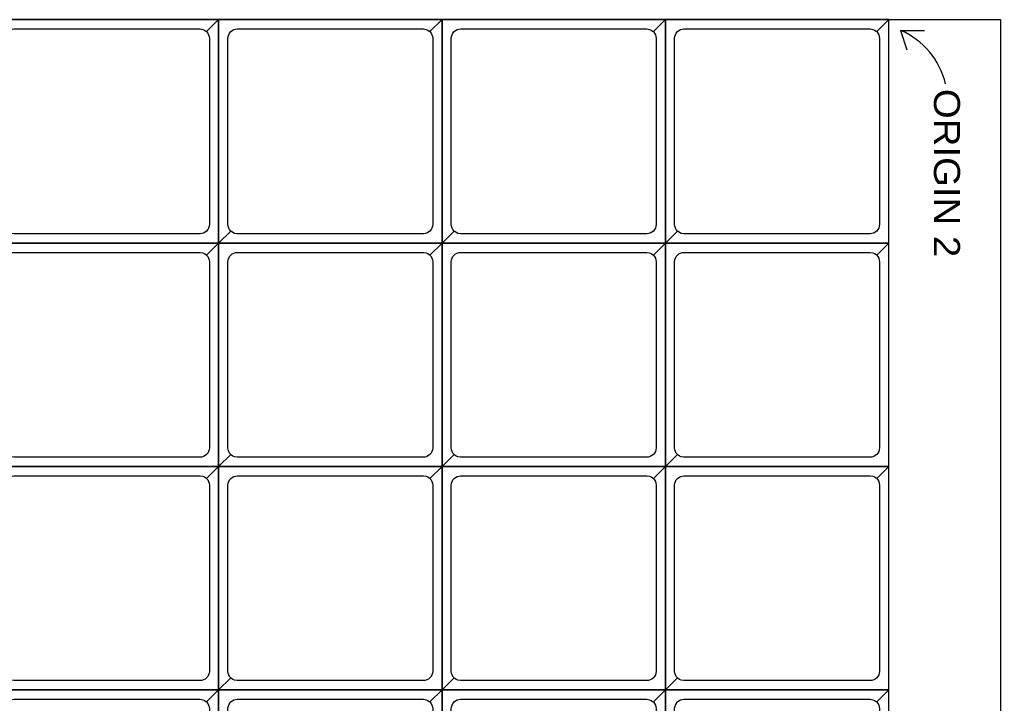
# Model space of a CAD drawing. Extents: x 67896 to 67908, y 49158.5 to 49162.6.
# Drawn here: x 67905.354 to 67907.989, y 49160.797 to 49162.633 of the extents above; entities that cross this region are included whole.
import ezdxf
from ezdxf.enums import TextEntityAlignment as Align

# ---------------------------------------------------------------- set-up
doc = ezdxf.new("R2010")
doc.units = 0
doc.header["$LTSCALE"] = 0.02
for name, color, linetype, lineweight in [('1', 7, 'Continuous', 25), ('2', 7, 'Continuous', 25), ('3', 7, 'Continuous', 25), ('4', 7, 'Continuous', 25), ('5', 7, 'Continuous', 25)]:
    doc.layers.add(name, color=color, linetype=linetype, lineweight=lineweight)

msp = doc.modelspace()

# ---------------------------------------------------------------- linework, layer by layer
at = {"layer": '1'}
for points in [[(67905.2889, 49162.0331), (67905.8889, 49162.0331), (67905.8889, 49162.6331), (67905.2889, 49162.6331)], [(67905.8889, 49162.0331), (67906.4889, 49162.0331), (67906.4889, 49162.6331), (67905.8889, 49162.6331)], [(67906.4889, 49162.0331), (67907.0889, 49162.0331), (67907.0889, 49162.6331), (67906.4889, 49162.6331)], [(67907.0889, 49162.0331), (67907.6889, 49162.0331), (67907.6889, 49162.6331), (67907.0889, 49162.6331)], [(67905.2889, 49161.4331), (67905.8889, 49161.4331), (67905.8889, 49162.0331), (67905.2889, 49162.0331)], [(67905.8889, 49161.4331), (67906.4889, 49161.4331), (67906.4889, 49162.0331), (67905.8889, 49162.0331)], [(67906.4889, 49161.4331), (67907.0889, 49161.4331), (67907.0889, 49162.0331), (67906.4889, 49162.0331)], [(67907.0889, 49161.4331), (67907.6889, 49161.4331), (67907.6889, 49162.0331), (67907.0889, 49162.0331)], [(67905.2889, 49160.8331), (67905.8889, 49160.8331), (67905.8889, 49161.4331), (67905.2889, 49161.4331)], [(67905.8889, 49160.8331), (67906.4889, 49160.8331), (67906.4889, 49161.4331), (67905.8889, 49161.4331)], [(67906.4889, 49160.8331), (67907.0889, 49160.8331), (67907.0889, 49161.4331), (67906.4889, 49161.4331)], [(67907.0889, 49160.8331), (67907.6889, 49160.8331), (67907.6889, 49161.4331), (67907.0889, 49161.4331)], [(67905.2889, 49160.2331), (67905.8889, 49160.2331), (67905.8889, 49160.8331), (67905.2889, 49160.8331)], [(67905.8889, 49160.2331), (67906.4889, 49160.2331), (67906.4889, 49160.8331), (67905.8889, 49160.8331)], [(67906.4889, 49160.2331), (67907.0889, 49160.2331), (67907.0889, 49160.8331), (67906.4889, 49160.8331)], [(67907.0889, 49160.2331), (67907.6889, 49160.2331), (67907.6889, 49160.8331), (67907.0889, 49160.8331)]]:
    msp.add_lwpolyline(points, close=True, dxfattribs=at)
at = {"layer": '2'}
for points in [[(67907.9889, 49159.0331), (67895.9889, 49159.0331), (67895.9889, 49162.6331), (67907.9889, 49162.6331)], [(67905.2889, 49162.0331), (67905.8889, 49162.0331), (67905.8889, 49162.6331), (67905.2889, 49162.6331)], [(67905.8889, 49162.0331), (67906.4889, 49162.0331), (67906.4889, 49162.6331), (67905.8889, 49162.6331)], [(67906.4889, 49162.0331), (67907.0889, 49162.0331), (67907.0889, 49162.6331), (67906.4889, 49162.6331)], [(67907.0889, 49162.0331), (67907.6889, 49162.0331), (67907.6889, 49162.6331), (67907.0889, 49162.6331)], [(67905.2889, 49161.4331), (67905.8889, 49161.4331), (67905.8889, 49162.0331), (67905.2889, 49162.0331)], [(67905.8889, 49161.4331), (67906.4889, 49161.4331), (67906.4889, 49162.0331), (67905.8889, 49162.0331)], [(67906.4889, 49161.4331), (67907.0889, 49161.4331), (67907.0889, 49162.0331), (67906.4889, 49162.0331)], [(67907.0889, 49161.4331), (67907.6889, 49161.4331), (67907.6889, 49162.0331), (67907.0889, 49162.0331)], [(67905.2889, 49160.8331), (67905.8889, 49160.8331), (67905.8889, 49161.4331), (67905.2889, 49161.4331)], [(67905.8889, 49160.8331), (67906.4889, 49160.8331), (67906.4889, 49161.4331), (67905.8889, 49161.4331)], [(67906.4889, 49160.8331), (67907.0889, 49160.8331), (67907.0889, 49161.4331), (67906.4889, 49161.4331)], [(67907.0889, 49160.8331), (67907.6889, 49160.8331), (67907.6889, 49161.4331), (67907.0889, 49161.4331)], [(67905.2889, 49160.2331), (67905.8889, 49160.2331), (67905.8889, 49160.8331), (67905.2889, 49160.8331)], [(67905.8889, 49160.2331), (67906.4889, 49160.2331), (67906.4889, 49160.8331), (67905.8889, 49160.8331)], [(67906.4889, 49160.2331), (67907.0889, 49160.2331), (67907.0889, 49160.8331), (67906.4889, 49160.8331)], [(67907.0889, 49160.2331), (67907.6889, 49160.2331), (67907.6889, 49160.8331), (67907.0889, 49160.8331)]]:
    msp.add_lwpolyline(points, close=True, dxfattribs=at)
at = {"layer": '3'}
for points in [[(67905.8889, 49162.6331), (67905.2889, 49162.6331), (67905.2889, 49162.0331), (67905.3212, 49162.0654), (67905.3181, 49162.0692), (67905.3158, 49162.0735), (67905.3144, 49162.0782), (67905.3139, 49162.0831), (67905.3139, 49162.5831), (67905.3144, 49162.588), (67905.3158, 49162.5927), (67905.3181, 49162.597), (67905.3212, 49162.6008), (67905.3212, 49162.6008), (67905.325, 49162.6039), (67905.3293, 49162.6062), (67905.334, 49162.6076), (67905.3389, 49162.6081), (67905.8389, 49162.6081), (67905.8462, 49162.607), (67905.8507, 49162.6051), (67905.8548, 49162.6024), (67905.8566, 49162.6008)], [(67906.4889, 49162.6331), (67905.8889, 49162.6331), (67905.8889, 49162.0331), (67905.9212, 49162.0654), (67905.9181, 49162.0692), (67905.9158, 49162.0735), (67905.9144, 49162.0782), (67905.9139, 49162.0831), (67905.9139, 49162.5831), (67905.9144, 49162.588), (67905.9158, 49162.5927), (67905.9181, 49162.597), (67905.9212, 49162.6008), (67905.9212, 49162.6008), (67905.925, 49162.6039), (67905.9293, 49162.6062), (67905.934, 49162.6076), (67905.9389, 49162.6081), (67906.4389, 49162.6081), (67906.4462, 49162.607), (67906.4507, 49162.6051), (67906.4548, 49162.6024), (67906.4566, 49162.6008)], [(67907.0889, 49162.6331), (67906.4889, 49162.6331), (67906.4889, 49162.0331), (67906.5212, 49162.0654), (67906.5181, 49162.0692), (67906.5158, 49162.0735), (67906.5144, 49162.0782), (67906.5139, 49162.0831), (67906.5139, 49162.5831), (67906.5144, 49162.588), (67906.5158, 49162.5927), (67906.5181, 49162.597), (67906.5212, 49162.6008), (67906.5212, 49162.6008), (67906.525, 49162.6039), (67906.5293, 49162.6062), (67906.534, 49162.6076), (67906.5389, 49162.6081), (67907.0389, 49162.6081), (67907.0462, 49162.607), (67907.0507, 49162.6051), (67907.0548, 49162.6024), (67907.0566, 49162.6008)], [(67907.6889, 49162.6331), (67907.0889, 49162.6331), (67907.0889, 49162.0331), (67907.1212, 49162.0654), (67907.1181, 49162.0692), (67907.1158, 49162.0735), (67907.1144, 49162.0782), (67907.1139, 49162.0831), (67907.1139, 49162.5831), (67907.1144, 49162.588), (67907.1158, 49162.5927), (67907.1181, 49162.597), (67907.1212, 49162.6008), (67907.1212, 49162.6008), (67907.125, 49162.6039), (67907.1293, 49162.6062), (67907.134, 49162.6076), (67907.1389, 49162.6081), (67907.6389, 49162.6081), (67907.6462, 49162.607), (67907.6507, 49162.6051), (67907.6548, 49162.6024), (67907.6566, 49162.6008)], [(67905.8889, 49162.0331), (67905.2889, 49162.0331), (67905.2889, 49161.4331), (67905.3212, 49161.4654), (67905.3181, 49161.4692), (67905.3158, 49161.4735), (67905.3144, 49161.4782), (67905.3139, 49161.4831), (67905.3139, 49161.9831), (67905.3144, 49161.988), (67905.3158, 49161.9927), (67905.3181, 49161.997), (67905.3212, 49162.0008), (67905.3212, 49162.0008), (67905.325, 49162.0039), (67905.3293, 49162.0062), (67905.334, 49162.0076), (67905.3389, 49162.0081), (67905.8389, 49162.0081), (67905.8462, 49162.007), (67905.8507, 49162.0051), (67905.8548, 49162.0024), (67905.8566, 49162.0008)], [(67906.4889, 49162.0331), (67905.8889, 49162.0331), (67905.8889, 49161.4331), (67905.9212, 49161.4654), (67905.9181, 49161.4692), (67905.9158, 49161.4735), (67905.9144, 49161.4782), (67905.9139, 49161.4831), (67905.9139, 49161.9831), (67905.9144, 49161.988), (67905.9158, 49161.9927), (67905.9181, 49161.997), (67905.9212, 49162.0008), (67905.9212, 49162.0008), (67905.925, 49162.0039), (67905.9293, 49162.0062), (67905.934, 49162.0076), (67905.9389, 49162.0081), (67906.4389, 49162.0081), (67906.4462, 49162.007), (67906.4507, 49162.0051), (67906.4548, 49162.0024), (67906.4566, 49162.0008)], [(67907.0889, 49162.0331), (67906.4889, 49162.0331), (67906.4889, 49161.4331), (67906.5212, 49161.4654), (67906.5181, 49161.4692), (67906.5158, 49161.4735), (67906.5144, 49161.4782), (67906.5139, 49161.4831), (67906.5139, 49161.9831), (67906.5144, 49161.988), (67906.5158, 49161.9927), (67906.5181, 49161.997), (67906.5212, 49162.0008), (67906.5212, 49162.0008), (67906.525, 49162.0039), (67906.5293, 49162.0062), (67906.534, 49162.0076), (67906.5389, 49162.0081), (67907.0389, 49162.0081), (67907.0462, 49162.007), (67907.0507, 49162.0051), (67907.0548, 49162.0024), (67907.0566, 49162.0008)], [(67907.6889, 49162.0331), (67907.0889, 49162.0331), (67907.0889, 49161.4331), (67907.1212, 49161.4654), (67907.1181, 49161.4692), (67907.1158, 49161.4735), (67907.1144, 49161.4782), (67907.1139, 49161.4831), (67907.1139, 49161.9831), (67907.1144, 49161.988), (67907.1158, 49161.9927), (67907.1181, 49161.997), (67907.1212, 49162.0008), (67907.1212, 49162.0008), (67907.125, 49162.0039), (67907.1293, 49162.0062), (67907.134, 49162.0076), (67907.1389, 49162.0081), (67907.6389, 49162.0081), (67907.6462, 49162.007), (67907.6507, 49162.0051), (67907.6548, 49162.0024), (67907.6566, 49162.0008)], [(67905.8889, 49161.4331), (67905.2889, 49161.4331), (67905.2889, 49160.8331), (67905.3212, 49160.8654), (67905.3181, 49160.8692), (67905.3158, 49160.8735), (67905.3144, 49160.8782), (67905.3139, 49160.8831), (67905.3139, 49161.3831), (67905.3144, 49161.388), (67905.3158, 49161.3927), (67905.3181, 49161.397), (67905.3212, 49161.4008), (67905.3212, 49161.4008), (67905.325, 49161.4039), (67905.3293, 49161.4062), (67905.334, 49161.4076), (67905.3389, 49161.4081), (67905.8389, 49161.4081), (67905.8462, 49161.407), (67905.8507, 49161.4051), (67905.8548, 49161.4024), (67905.8566, 49161.4008)], [(67906.4889, 49161.4331), (67905.8889, 49161.4331), (67905.8889, 49160.8331), (67905.9212, 49160.8654), (67905.9181, 49160.8692), (67905.9158, 49160.8735), (67905.9144, 49160.8782), (67905.9139, 49160.8831), (67905.9139, 49161.3831), (67905.9144, 49161.388), (67905.9158, 49161.3927), (67905.9181, 49161.397), (67905.9212, 49161.4008), (67905.9212, 49161.4008), (67905.925, 49161.4039), (67905.9293, 49161.4062), (67905.934, 49161.4076), (67905.9389, 49161.4081), (67906.4389, 49161.4081), (67906.4462, 49161.407), (67906.4507, 49161.4051), (67906.4548, 49161.4024), (67906.4566, 49161.4008)], [(67907.0889, 49161.4331), (67906.4889, 49161.4331), (67906.4889, 49160.8331), (67906.5212, 49160.8654), (67906.5181, 49160.8692), (67906.5158, 49160.8735), (67906.5144, 49160.8782), (67906.5139, 49160.8831), (67906.5139, 49161.3831), (67906.5144, 49161.388), (67906.5158, 49161.3927), (67906.5181, 49161.397), (67906.5212, 49161.4008), (67906.5212, 49161.4008), (67906.525, 49161.4039), (67906.5293, 49161.4062), (67906.534, 49161.4076), (67906.5389, 49161.4081), (67907.0389, 49161.4081), (67907.0462, 49161.407), (67907.0507, 49161.4051), (67907.0548, 49161.4024), (67907.0566, 49161.4008)], [(67907.6889, 49161.4331), (67907.0889, 49161.4331), (67907.0889, 49160.8331), (67907.1212, 49160.8654), (67907.1181, 49160.8692), (67907.1158, 49160.8735), (67907.1144, 49160.8782), (67907.1139, 49160.8831), (67907.1139, 49161.3831), (67907.1144, 49161.388), (67907.1158, 49161.3927), (67907.1181, 49161.397), (67907.1212, 49161.4008), (67907.1212, 49161.4008), (67907.125, 49161.4039), (67907.1293, 49161.4062), (67907.134, 49161.4076), (67907.1389, 49161.4081), (67907.6389, 49161.4081), (67907.6462, 49161.407), (67907.6507, 49161.4051), (67907.6548, 49161.4024), (67907.6566, 49161.4008)], [(67905.8889, 49160.8331), (67905.2889, 49160.8331), (67905.2889, 49160.2331), (67905.3212, 49160.2654), (67905.3181, 49160.2692), (67905.3158, 49160.2735), (67905.3144, 49160.2782), (67905.3139, 49160.2831), (67905.3139, 49160.7831), (67905.3144, 49160.788), (67905.3158, 49160.7927), (67905.3181, 49160.797), (67905.3212, 49160.8008), (67905.3212, 49160.8008), (67905.325, 49160.8039), (67905.3293, 49160.8062), (67905.334, 49160.8076), (67905.3389, 49160.8081), (67905.8389, 49160.8081), (67905.8462, 49160.807), (67905.8507, 49160.8051), (67905.8548, 49160.8024), (67905.8566, 49160.8008)], [(67906.4889, 49160.8331), (67905.8889, 49160.8331), (67905.8889, 49160.2331), (67905.9212, 49160.2654), (67905.9181, 49160.2692), (67905.9158, 49160.2735), (67905.9144, 49160.2782), (67905.9139, 49160.2831), (67905.9139, 49160.7831), (67905.9144, 49160.788), (67905.9158, 49160.7927), (67905.9181, 49160.797), (67905.9212, 49160.8008), (67905.9212, 49160.8008), (67905.925, 49160.8039), (67905.9293, 49160.8062), (67905.934, 49160.8076), (67905.9389, 49160.8081), (67906.4389, 49160.8081), (67906.4462, 49160.807), (67906.4507, 49160.8051), (67906.4548, 49160.8024), (67906.4566, 49160.8008)], [(67907.0889, 49160.8331), (67906.4889, 49160.8331), (67906.4889, 49160.2331), (67906.5212, 49160.2654), (67906.5181, 49160.2692), (67906.5158, 49160.2735), (67906.5144, 49160.2782), (67906.5139, 49160.2831), (67906.5139, 49160.7831), (67906.5144, 49160.788), (67906.5158, 49160.7927), (67906.5181, 49160.797), (67906.5212, 49160.8008), (67906.5212, 49160.8008), (67906.525, 49160.8039), (67906.5293, 49160.8062), (67906.534, 49160.8076), (67906.5389, 49160.8081), (67907.0389, 49160.8081), (67907.0462, 49160.807), (67907.0507, 49160.8051), (67907.0548, 49160.8024), (67907.0566, 49160.8008)], [(67907.6889, 49160.8331), (67907.0889, 49160.8331), (67907.0889, 49160.2331), (67907.1212, 49160.2654), (67907.1181, 49160.2692), (67907.1158, 49160.2735), (67907.1144, 49160.2782), (67907.1139, 49160.2831), (67907.1139, 49160.7831), (67907.1144, 49160.788), (67907.1158, 49160.7927), (67907.1181, 49160.797), (67907.1212, 49160.8008), (67907.1212, 49160.8008), (67907.125, 49160.8039), (67907.1293, 49160.8062), (67907.134, 49160.8076), (67907.1389, 49160.8081), (67907.6389, 49160.8081), (67907.6462, 49160.807), (67907.6507, 49160.8051), (67907.6548, 49160.8024), (67907.6566, 49160.8008)]]:
    msp.add_lwpolyline(points, close=True, dxfattribs=at)
at = {"layer": '4'}
for points in [[(67905.2889, 49162.0331), (67905.8889, 49162.0331), (67905.8889, 49162.6331), (67905.8566, 49162.6008), (67905.8597, 49162.597), (67905.862, 49162.5927), (67905.8634, 49162.588), (67905.8639, 49162.5831), (67905.8639, 49162.0831), (67905.8634, 49162.0782), (67905.862, 49162.0735), (67905.8597, 49162.0692), (67905.8566, 49162.0654), (67905.8566, 49162.0654), (67905.8528, 49162.0623), (67905.8485, 49162.06), (67905.8438, 49162.0586), (67905.8389, 49162.0581), (67905.3389, 49162.0581), (67905.3316, 49162.0592), (67905.3271, 49162.0611), (67905.323, 49162.0638), (67905.3212, 49162.0654)], [(67905.8889, 49162.0331), (67906.4889, 49162.0331), (67906.4889, 49162.6331), (67906.4566, 49162.6008), (67906.4597, 49162.597), (67906.462, 49162.5927), (67906.4634, 49162.588), (67906.4639, 49162.5831), (67906.4639, 49162.0831), (67906.4634, 49162.0782), (67906.462, 49162.0735), (67906.4597, 49162.0692), (67906.4566, 49162.0654), (67906.4566, 49162.0654), (67906.4528, 49162.0623), (67906.4485, 49162.06), (67906.4438, 49162.0586), (67906.4389, 49162.0581), (67905.9389, 49162.0581), (67905.9316, 49162.0592), (67905.9271, 49162.0611), (67905.923, 49162.0638), (67905.9212, 49162.0654)], [(67906.4889, 49162.0331), (67907.0889, 49162.0331), (67907.0889, 49162.6331), (67907.0566, 49162.6008), (67907.0597, 49162.597), (67907.062, 49162.5927), (67907.0634, 49162.588), (67907.0639, 49162.5831), (67907.0639, 49162.0831), (67907.0634, 49162.0782), (67907.062, 49162.0735), (67907.0597, 49162.0692), (67907.0566, 49162.0654), (67907.0566, 49162.0654), (67907.0528, 49162.0623), (67907.0485, 49162.06), (67907.0438, 49162.0586), (67907.0389, 49162.0581), (67906.5389, 49162.0581), (67906.5316, 49162.0592), (67906.5271, 49162.0611), (67906.523, 49162.0638), (67906.5212, 49162.0654)], [(67907.0889, 49162.0331), (67907.6889, 49162.0331), (67907.6889, 49162.6331), (67907.6566, 49162.6008), (67907.6597, 49162.597), (67907.662, 49162.5927), (67907.6634, 49162.588), (67907.6639, 49162.5831), (67907.6639, 49162.0831), (67907.6634, 49162.0782), (67907.662, 49162.0735), (67907.6597, 49162.0692), (67907.6566, 49162.0654), (67907.6566, 49162.0654), (67907.6528, 49162.0623), (67907.6485, 49162.06), (67907.6438, 49162.0586), (67907.6389, 49162.0581), (67907.1389, 49162.0581), (67907.1316, 49162.0592), (67907.1271, 49162.0611), (67907.123, 49162.0638), (67907.1212, 49162.0654)], [(67905.2889, 49161.4331), (67905.8889, 49161.4331), (67905.8889, 49162.0331), (67905.8566, 49162.0008), (67905.8597, 49161.997), (67905.862, 49161.9927), (67905.8634, 49161.988), (67905.8639, 49161.9831), (67905.8639, 49161.4831), (67905.8634, 49161.4782), (67905.862, 49161.4735), (67905.8597, 49161.4692), (67905.8566, 49161.4654), (67905.8566, 49161.4654), (67905.8528, 49161.4623), (67905.8485, 49161.46), (67905.8438, 49161.4586), (67905.8389, 49161.4581), (67905.3389, 49161.4581), (67905.3316, 49161.4592), (67905.3271, 49161.4611), (67905.323, 49161.4638), (67905.3212, 49161.4654)], [(67905.8889, 49161.4331), (67906.4889, 49161.4331), (67906.4889, 49162.0331), (67906.4566, 49162.0008), (67906.4597, 49161.997), (67906.462, 49161.9927), (67906.4634, 49161.988), (67906.4639, 49161.9831), (67906.4639, 49161.4831), (67906.4634, 49161.4782), (67906.462, 49161.4735), (67906.4597, 49161.4692), (67906.4566, 49161.4654), (67906.4566, 49161.4654), (67906.4528, 49161.4623), (67906.4485, 49161.46), (67906.4438, 49161.4586), (67906.4389, 49161.4581), (67905.9389, 49161.4581), (67905.9316, 49161.4592), (67905.9271, 49161.4611), (67905.923, 49161.4638), (67905.9212, 49161.4654)], [(67906.4889, 49161.4331), (67907.0889, 49161.4331), (67907.0889, 49162.0331), (67907.0566, 49162.0008), (67907.0597, 49161.997), (67907.062, 49161.9927), (67907.0634, 49161.988), (67907.0639, 49161.9831), (67907.0639, 49161.4831), (67907.0634, 49161.4782), (67907.062, 49161.4735), (67907.0597, 49161.4692), (67907.0566, 49161.4654), (67907.0566, 49161.4654), (67907.0528, 49161.4623), (67907.0485, 49161.46), (67907.0438, 49161.4586), (67907.0389, 49161.4581), (67906.5389, 49161.4581), (67906.5316, 49161.4592), (67906.5271, 49161.4611), (67906.523, 49161.4638), (67906.5212, 49161.4654)], [(67907.0889, 49161.4331), (67907.6889, 49161.4331), (67907.6889, 49162.0331), (67907.6566, 49162.0008), (67907.6597, 49161.997), (67907.662, 49161.9927), (67907.6634, 49161.988), (67907.6639, 49161.9831), (67907.6639, 49161.4831), (67907.6634, 49161.4782), (67907.662, 49161.4735), (67907.6597, 49161.4692), (67907.6566, 49161.4654), (67907.6566, 49161.4654), (67907.6528, 49161.4623), (67907.6485, 49161.46), (67907.6438, 49161.4586), (67907.6389, 49161.4581), (67907.1389, 49161.4581), (67907.1316, 49161.4592), (67907.1271, 49161.4611), (67907.123, 49161.4638), (67907.1212, 49161.4654)], [(67905.2889, 49160.8331), (67905.8889, 49160.8331), (67905.8889, 49161.4331), (67905.8566, 49161.4008), (67905.8597, 49161.397), (67905.862, 49161.3927), (67905.8634, 49161.388), (67905.8639, 49161.3831), (67905.8639, 49160.8831), (67905.8634, 49160.8782), (67905.862, 49160.8735), (67905.8597, 49160.8692), (67905.8566, 49160.8654), (67905.8566, 49160.8654), (67905.8528, 49160.8623), (67905.8485, 49160.86), (67905.8438, 49160.8586), (67905.8389, 49160.8581), (67905.3389, 49160.8581), (67905.3316, 49160.8592), (67905.3271, 49160.8611), (67905.323, 49160.8638), (67905.3212, 49160.8654)], [(67905.8889, 49160.8331), (67906.4889, 49160.8331), (67906.4889, 49161.4331), (67906.4566, 49161.4008), (67906.4597, 49161.397), (67906.462, 49161.3927), (67906.4634, 49161.388), (67906.4639, 49161.3831), (67906.4639, 49160.8831), (67906.4634, 49160.8782), (67906.462, 49160.8735), (67906.4597, 49160.8692), (67906.4566, 49160.8654), (67906.4566, 49160.8654), (67906.4528, 49160.8623), (67906.4485, 49160.86), (67906.4438, 49160.8586), (67906.4389, 49160.8581), (67905.9389, 49160.8581), (67905.9316, 49160.8592), (67905.9271, 49160.8611), (67905.923, 49160.8638), (67905.9212, 49160.8654)], [(67906.4889, 49160.8331), (67907.0889, 49160.8331), (67907.0889, 49161.4331), (67907.0566, 49161.4008), (67907.0597, 49161.397), (67907.062, 49161.3927), (67907.0634, 49161.388), (67907.0639, 49161.3831), (67907.0639, 49160.8831), (67907.0634, 49160.8782), (67907.062, 49160.8735), (67907.0597, 49160.8692), (67907.0566, 49160.8654), (67907.0566, 49160.8654), (67907.0528, 49160.8623), (67907.0485, 49160.86), (67907.0438, 49160.8586), (67907.0389, 49160.8581), (67906.5389, 49160.8581), (67906.5316, 49160.8592), (67906.5271, 49160.8611), (67906.523, 49160.8638), (67906.5212, 49160.8654)], [(67907.0889, 49160.8331), (67907.6889, 49160.8331), (67907.6889, 49161.4331), (67907.6566, 49161.4008), (67907.6597, 49161.397), (67907.662, 49161.3927), (67907.6634, 49161.388), (67907.6639, 49161.3831), (67907.6639, 49160.8831), (67907.6634, 49160.8782), (67907.662, 49160.8735), (67907.6597, 49160.8692), (67907.6566, 49160.8654), (67907.6566, 49160.8654), (67907.6528, 49160.8623), (67907.6485, 49160.86), (67907.6438, 49160.8586), (67907.6389, 49160.8581), (67907.1389, 49160.8581), (67907.1316, 49160.8592), (67907.1271, 49160.8611), (67907.123, 49160.8638), (67907.1212, 49160.8654)], [(67905.2889, 49160.2331), (67905.8889, 49160.2331), (67905.8889, 49160.8331), (67905.8566, 49160.8008), (67905.8597, 49160.797), (67905.862, 49160.7927), (67905.8634, 49160.788), (67905.8639, 49160.7831), (67905.8639, 49160.2831), (67905.8634, 49160.2782), (67905.862, 49160.2735), (67905.8597, 49160.2692), (67905.8566, 49160.2654), (67905.8566, 49160.2654), (67905.8528, 49160.2623), (67905.8485, 49160.26), (67905.8438, 49160.2586), (67905.8389, 49160.2581), (67905.3389, 49160.2581), (67905.3316, 49160.2592), (67905.3271, 49160.2611), (67905.323, 49160.2638), (67905.3212, 49160.2654)], [(67905.8889, 49160.2331), (67906.4889, 49160.2331), (67906.4889, 49160.8331), (67906.4566, 49160.8008), (67906.4597, 49160.797), (67906.462, 49160.7927), (67906.4634, 49160.788), (67906.4639, 49160.7831), (67906.4639, 49160.2831), (67906.4634, 49160.2782), (67906.462, 49160.2735), (67906.4597, 49160.2692), (67906.4566, 49160.2654), (67906.4566, 49160.2654), (67906.4528, 49160.2623), (67906.4485, 49160.26), (67906.4438, 49160.2586), (67906.4389, 49160.2581), (67905.9389, 49160.2581), (67905.9316, 49160.2592), (67905.9271, 49160.2611), (67905.923, 49160.2638), (67905.9212, 49160.2654)], [(67906.4889, 49160.2331), (67907.0889, 49160.2331), (67907.0889, 49160.8331), (67907.0566, 49160.8008), (67907.0597, 49160.797), (67907.062, 49160.7927), (67907.0634, 49160.788), (67907.0639, 49160.7831), (67907.0639, 49160.2831), (67907.0634, 49160.2782), (67907.062, 49160.2735), (67907.0597, 49160.2692), (67907.0566, 49160.2654), (67907.0566, 49160.2654), (67907.0528, 49160.2623), (67907.0485, 49160.26), (67907.0438, 49160.2586), (67907.0389, 49160.2581), (67906.5389, 49160.2581), (67906.5316, 49160.2592), (67906.5271, 49160.2611), (67906.523, 49160.2638), (67906.5212, 49160.2654)], [(67907.0889, 49160.2331), (67907.6889, 49160.2331), (67907.6889, 49160.8331), (67907.6566, 49160.8008), (67907.6597, 49160.797), (67907.662, 49160.7927), (67907.6634, 49160.788), (67907.6639, 49160.7831), (67907.6639, 49160.2831), (67907.6634, 49160.2782), (67907.662, 49160.2735), (67907.6597, 49160.2692), (67907.6566, 49160.2654), (67907.6566, 49160.2654), (67907.6528, 49160.2623), (67907.6485, 49160.26), (67907.6438, 49160.2586), (67907.6389, 49160.2581), (67907.1389, 49160.2581), (67907.1316, 49160.2592), (67907.1271, 49160.2611), (67907.123, 49160.2638), (67907.1212, 49160.2654)]]:
    msp.add_lwpolyline(points, close=True, dxfattribs=at)
at = {"layer": '5'}
for q in [(67907.7851, 49162.6042), (67907.7379, 49162.5522)]:
    msp.add_line((67907.7206, 49162.6042), q, dxfattribs=at)
msp.add_arc((67907.6388, 49162.4122), 0.2087, 13.472, 66.9361, dxfattribs=at)

# ---------------------------------------------------------------- texts
at = {"layer": '5', "width": 1.1}
msp.add_text('ORIGIN 2', height=0.07, rotation=270, dxfattribs=at).set_placement((67907.8104, 49162.2211), align=Align.CENTER)

doc.saveas('drawing.dxf')
